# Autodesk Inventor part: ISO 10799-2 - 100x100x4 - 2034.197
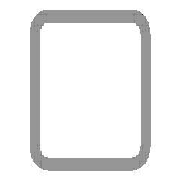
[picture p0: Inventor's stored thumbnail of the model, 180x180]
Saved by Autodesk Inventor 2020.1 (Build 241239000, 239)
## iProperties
Created: 2019-10
Part Number: ISO 10799-2 - 100x100x4 - 2034.197
Material: Stainless Steel
Description: Structural steels - Cold-formed, welded, structural hollow sections
Document SubType Name: Modeling
Standard: ISO
Designer: Synergysoft Dell02
Standard Revision: First edition 2011-09-15
Standards Organization: ISO
Language: en-US
Size Designation: 100x100x4
Categories: <MemberInstance><Categories><Category DisplayName="Structural Shapes" InternalName="089c4875-fa83-4c05-b084-43b9cc11f5ed" Mnemonic="GRDR"><CategoryParameter Dis
Stock Number: 100x100x4
Density: 8 g/cm^3
Appearance: Semi-Polished
_CCFamilyMember: 43
_CCFamilyDisplayName: ISO 10799-2 (Square) - Structural steels - Cold-formed, welded, structural hollow sections
_FrameMemberDoc: Frame Member File
_Version: 15.0.0
_GetPNFromCC: 1
G_L: 2034.197 mm
G_W: 100.000 mm
G_H: 100.000 mm
+AEA212C9-D0A0-4C01-827D-27FB334FF18B+CUTDETAIL1: Cut Angle 90.00 deg
+FAF08312-805B-409A-AF2E-A7754198D9AC+CUTDETAIL2: Miter 22.50 deg
+CF5D411B-9392-4AC4-A468-38BA15CBF984+CUTDETAIL3: Miter 45.00 deg
+2AC6C781-26F2-4D3A-9D4C-D9242D248150+CUTDETAIL4: Cut Angle 45.00 deg
IsCustomPart: 1
Author: Synergysoft Dell02
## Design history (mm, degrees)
node "Start Plane"
node "End Plane"
sketch "Sketch"
  geometry: L1 (-50, -42)-(-50, 42); L2 (-42, 50)-(42, 50); L3 (50, 42)-(50, -42); L4 (42, -50)-(-42, -50); L5 (-42, 46)-(42, 46); L6 (46, 42)-(46, -42); L7 (42, -46)-(-42, -46); L8 (-46, -42)-(-46, 42); L9 (0, 72.32)-(0, -72.32) reference; L10 (-72.32, 0)-(72.32, 0) reference; A1 r 8 centre (-42, -42) between (-50, -42) and (-42, -50); A2 r 8 centre (42, 42) between (50, 42) and (42, 50); A3 r 8 centre (-42, 42) between (-42, 50) and (-50, 42); A4 r 8 centre (42, -42) between (42, -50) and (50, -42); A5 r 4 centre (-42, 42) between (-42, 46) and (-46, 42); A6 r 4 centre (42, 42) between (46, 42) and (42, 46); A7 r 4 centre (42, -42) between (42, -46) and (46, -42); A8 r 4 centre (-42, -42) between (-46, -42) and (-42, -46)
  constraints: 16 end point, 16 point on circle, 8 centre point, 8 tangent, 4 parallel, 3 equal radius, 2 perpendicular, 7 other
  dimensions: "d7" = 8 radius of A1 (= G_IR); "d9" = 100 distance between parallel lines of L1 L3 (= G_W); "d11" = 100 distance between parallel lines of L2 L4 (= G_H); "d12" = 4 distance between parallel lines of L3 L6 (= G_T); "d15" = 50 distance between parallel lines of L9 L3 (= 0.5 x d9); "d16" = 50 distance between parallel lines of L2 L10 (= 0.5 x d11)
extrude "Body" new body sketch "Sketch" stored distance "d3" = 2034.19724 (= G_L); taper "d4" = 0 deg
node "Driven Length"
  sketch "Sketch3"
    geometry: L1 (0, 0)-(10, 0) reference
    constraints: 2 end point, 1 horizontal
  workplane "Work Plane3"
  sketch "Sketch4"
    geometry: L1 (-2, 37.123)-(12, 37.123) reference; L2 (-2, 2071.32)-(12, 2071.32) reference
    dimensions: "d18" = 2034.19724 distance between parallel lines of L1 L2 (derived)
workplane "Work Plane4"
split "Split1"
workplane "Work Plane5"
split "Split2"
workplane "Work Plane6"
split "Split3"
workplane "Work Plane7"
split "Split4"
body "Solid1"
other parameters: "G_W" = 100 [user parameter; used in 1 equation term], "G_H" = 100 [user parameter; used in 1 equation term], "G_T" = 4 [user parameter; used in 1 equation term], "G_IR" = 8 [user parameter; used in 1 equation term], "G_L" = 2034.19724 (= d18) [user parameter; used in 1 equation term], "G_OFFSET_START" = -37.12311 [user parameter; used in 1 equation term], "d13" = 37.12311 (= -G_OFFSET_START), "d14" = 2071.32034 (= G_OFFSET_END + B_L), "B_L" = 2121.32034 [user parameter; used in 1 equation term], "d17" = 90 deg, "MAS" = 1.17 [user parameter]
